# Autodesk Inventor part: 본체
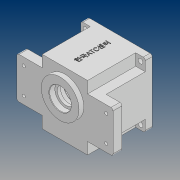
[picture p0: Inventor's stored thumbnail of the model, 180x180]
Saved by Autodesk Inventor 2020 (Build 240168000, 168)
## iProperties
Created: 2020-07
Part Number: 본체
Material: 일반
Document SubType Name: Modeling
Designer: PC312-
Density: 1 g/cm^3
Appearance: 기본값
Mass: 324.574 g
Surface Area: 793.93 cm^2
Volume: 324.574 cm^3
Author: PC312-
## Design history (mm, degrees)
sketch "스케치1"
  geometry: L1 (-47, 47)-(47, 47); L2 (47, 47)-(47, -47); L3 (47, -47)-(-47, -47); L4 (-47, -47)-(-47, 47); L5 (-47, 47)-(47, -47); L6 (47, 47)-(-47, -47); 1 further point
  constraints: 12 end point, 2 midpoint, 2 parallel, 1 horizontal, 1 perpendicular
  dimensions: "d0" = 94 distance of L1.start L1.end; "d1" = 94 distance of L1.end L2.end
extrude "돌출1" new body sketch "스케치1" distance "d2" = 80; taper "d3" = 0 deg
sketch "스케치2"
  geometry: L1 (-70, 30)-(70, 30); L2 (70, 30)-(70, -30); L3 (70, -30)-(-70, -30); L4 (-70, -30)-(-70, 30); L5 (-70, 30)-(70, -30); L6 (70, 30)-(-70, -30); 1 further point
  constraints: 12 end point, 2 midpoint, 2 parallel, 1 horizontal, 1 perpendicular
  dimensions: "d4" = 60 distance of L1.end L2.end; "d5" = 140 distance of L2.end L3.end
extrude "돌출2" join sketch "스케치2" distance "d6" = 13; taper "d7" = 0 deg
sketch "스케치3"
  geometry: C1 r 27.5 at (0, 11); 1 further point
  constraints: 1 centre point, 1 vertical alignment
  dimensions: "d8" = 55 diameter of C1; "d9" = 11 distance of point (0, 0) C1.centre
extrude "돌출3" join sketch "스케치3" distance "d10" = 7; taper "d11" = 0 deg
sketch "스케치4"
  geometry: L1 (33, 47)-(47, 47); L2 (47, 47)-(47, 30); L3 (47, 30)-(33, 30); L4 (33, 30)-(33, 47); L5 (47, 30)-(47, 47) reference; L6 (47, 47)-(-47, 47) reference; L7 (-47, 47)-(-33, 47); L8 (-33, 47)-(-33, 30); L9 (-33, 30)-(-47, 30); L10 (-47, 30)-(-47, 47); L11 (-47, -47)-(-47, 47) reference; 3 further points
  constraints: 16 end point, 4 collinear, 4 parallel, 2 horizontal, 2 perpendicular
  dimensions: "d12" = 33 distance from line of point (0, 0) L4; "d13" = 30 distance from line of point (0, 0) L3; "d14" = 33 distance from line of point (0, 0) L8; "d15" = 30 distance from line of point (0, 0) L9
extrude "돌출4" cut sketch "스케치4" distance "d16" = 70; taper "d17" = 0 deg
node "스케치5"
sketch "스케치6"
  geometry: C1 r 43 at (0, 0); 1 further point
  constraints: 1 centre point, 1 coincident
  dimensions: "d23" = 86 diameter of C1
extrude "돌출5" cut sketch "스케치6" distance "d24" = 9; taper "d25" = 0 deg
sketch "스케치7"
  geometry: C1 r 40 at (0, 0); 1 further point
  constraints: 1 centre point, 1 coincident
  dimensions: "d26" = 80 diameter of C1
extrude "돌출6" cut sketch "스케치7" distance "d27" = 62; taper "d28" = 0 deg
sketch "스케치8"
  geometry: A1 r 21 centre (0, 11) between (8.978, -7.984) and (-8.978, -7.984); A2 r 15 centre (0, -20) between (-8.978, -7.984) and (8.978, -7.984); 1 further point
  constraints: 4 point on circle, 2 centre point, 2 vertical alignment
  dimensions: "d29" = 11 distance of point (0, 0) A1.centre; "d30" = 20 distance of A2.centre point (0, 0); "d31" = 42 diameter of A1; "d32" = 30 diameter of A2
extrude "돌출7" join sketch "스케치8" distance "d33" = 7; taper "d34" = 0 deg
sketch "스케치9"
  geometry: C1 r 27.5 at (0, 0) reference; C2 r 16 at (0, 0); 1 further point
  constraints: 1 centre point, 1 coincident
  dimensions: "d35" = 32 diameter of C2
extrude "돌출8" cut sketch "스케치9" distance "d36" = 8.3; taper "d37" = 0 deg
sketch "스케치10"
  geometry: C1 r 12.5 at (0, 0); C2 r 16 at (0, 0) reference; 1 further point
  constraints: 1 centre point, 1 coincident
  dimensions: "d38" = 25 diameter of C1
extrude "돌출9" cut sketch "스케치10" distance "d39" = 4.7; taper "d40" = 0 deg
sketch "스케치11"
  geometry: C1 r 12.5 at (0, 0) reference; C2 r 17.5 at (0, 0); 1 further point
  constraints: 1 centre point, 1 coincident
  dimensions: "d41" = 35 diameter of C2
extrude "돌출11" cut sketch "스케치11" distance "d44" = 10; taper "d45" = 0 deg
sketch "스케치12"
  geometry: C1 r 11 at (0, -20); A1 r 15 centre (0, -20) between (-8.978, -7.984) and (8.978, -7.984) reference; 1 further point
  constraints: 1 centre point, 1 coincident
  dimensions: "d46" = 22 diameter of C1
extrude "돌출12" cut sketch "스케치12" distance "d47" = 7; taper "d48" = 0 deg
sketch "스케치13"
  geometry: C1 r 11 at (0, 0) reference; C2 r 9.5 at (0, 0); 1 further point
  constraints: 1 centre point, 1 coincident
  dimensions: "d49" = 19 diameter of C2
extrude "돌출13" cut sketch "스케치13" distance "d50" = 3; taper "d51" = 0 deg
sketch "스케치14"
  geometry: A1 r 4 centre (36, 0) between (36.19, 3.995) and (36.19, -3.995); A2 r 36 centre (0, 0) between (36, 0) and (35.772, 4.045); A3 r 3 centre (36.333, 6.992) between (35.772, 4.045) and (39.279, 7.559); A4 r 40 centre (0, 0) between (39.279, 7.559) and (39.279, -7.559) reference; A5 r 3 centre (36.333, -6.992) between (39.279, -7.559) and (35.772, -4.045); 1 further point
  constraints: 13 point on circle, 4 centre point, 4 tangent, 1 coincident, 1 horizontal alignment
  dimensions: "d52" = 72 diameter of A2; "d53" = 8 diameter of A1; "d55" = 6 diameter of A3; "d56" = 6 diameter of A5
extrude "돌출14" join sketch "스케치14" stored distance "d57" = 3; taper "d58" = 0 deg
fillet "모깎기1" dims "d59" = 3
sketch "스케치16"
  geometry: C1 r 3.5 at (40, 40); A1 r 3 centre (44, 44) between (47, 44) and (44, 47) reference; 1 further point
  constraints: 1 centre point
  dimensions: "d62" = 7 diameter of C1; "d63" = 40 horizontal distance of point (0, 0) C1.centre; "d64" = 40 horizontal distance of C1.centre point (0, 0)
extrude "돌출15" cut sketch "스케치16" extent not by distance; stored distance "d65" = 0; taper "d66" = 0 deg
sketch "스케치17"
  geometry: 2 further points
  dimensions: "d73" = 19 vertical distance of point (0, 0) point (-60, 19); "d74" = 60 horizontal distance of point (-60, 19) point (0, 0)
hole "구멍1" sketch "스케치17" at (-60, 19) diameter "d75" = 4.5; stored, may be unused: countersink angle "d79" = 90 deg, drill point angle "d81" = 0 deg; dims "d76" = 7, "d77" = 10, "d78" = 5, "d80" = 15
sketch "스케치18"
  geometry: A1 r 4 centre (-36, 0) between (-36.19, -3.995) and (-36.19, 3.995) reference; 2 further points
  constraints: 1 coincident
hole "구멍2" sketch "스케치18" at (-36, 0) diameter "d91" = 3.242; stored, may be unused: countersink angle "d95" = 90 deg, drill point angle "d97" = 118 deg; dims "d92" = 7, "d93" = 10, "d94" = 5, "d96" = 9
chamfer "모따기2" distance "d98" = 1; stored, may be unused: second distance "d99" = 2, angle "d100" = 45 deg
fillet "모깎기2" dims "d107" = 3
node "작업 평면1"
sketch "스케치19"
  geometry: L1 (-11, 80)-(77, 80) reference; 2 further points
  constraints: 1 vertical alignment, 1 other
  dimensions: "d109" = 40 distance from line of L1 point (33, 40)
feature "엠보싱1" sketch "스케치19" dims "d110" = 0.5, "d111" = 0
chamfer "모따기5" distance "d112" = 0.8; stored, may be unused: second distance "d113" = 2, angle "d114" = 30 deg
fillet "모깎기3" dims "d115" = 3
chamfer "모따기6" distance "d116" = 1; stored, may be unused: second distance "d117" = 2, angle "d118" = 30 deg
node "솔리드1"
mirror "미러1"
mirror "미러2"
pattern_linear "직사각형 패턴1" dims "d69" = 80, "d72" = 80
pattern_linear "직사각형 패턴2" dims "d84" = 38, "d87" = 120
mirror "미러3"
feature "A9D066F2-1C7D-4E18-AEED-F7BC21143FA4" dims "d75" = 4.5, "d76" = 7, "d77" = 10, "d78" = 5, "d79" = 90 deg, "d80" = 15, "d81" = 0
other parameters: "d108" = 5
